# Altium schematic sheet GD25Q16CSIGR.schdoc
size 127 x 101 mm
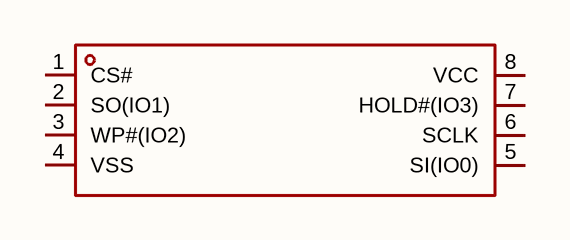
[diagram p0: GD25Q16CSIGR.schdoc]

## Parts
U?  gd25q16csigr  [SOP-8_L5.3-W5.3-P1.27-LS8.0-BL]  (value not drawn)

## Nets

Not connected (* = marked no-connect by the designer): U? 1(CS#) 2(SO(IO1)) 3(WP#(IO2)) 4(VSS) 5(SI(IO0)) 6(SCLK) 7(HOLD#(IO3)) 8(VCC)

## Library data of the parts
U? = gd25q16csigr: 接口类型:SPI;存储容量:16Mbit;时钟频率(fc):120MHz;; Manufacturer: GigaDevice(兆易创新); AddInBom: yes; ModelId: e456afcfff5840a795bdd4917416584f; ModelName: SOP-8_L5.2-W5.3-H2.1-LS7.9-P1.27; ModelTransform: 311.024,204.724,0,90,0,0,0,0.0005,0; Interface: SPI; Memory Size: 16Mbit; Clock Frequency: 120MHz; Voltage - Supply: 2.7V~3.6V; Standby Supply Current: 1uA; Program / Erase Cycles: 100000次; Page Programming Time (Tpp): 600us; Data Retention - TDR (Year): 20年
